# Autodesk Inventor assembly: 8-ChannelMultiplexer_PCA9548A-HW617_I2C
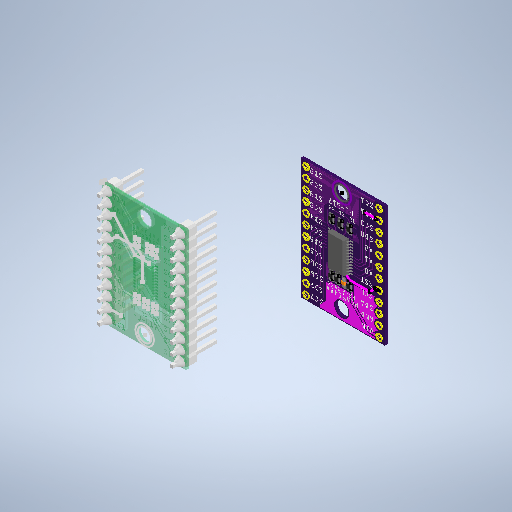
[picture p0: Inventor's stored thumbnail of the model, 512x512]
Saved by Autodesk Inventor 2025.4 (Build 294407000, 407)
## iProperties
Company: unknown
Created: 2023-08
Part Number: 8-ChannelMultiplexer_PCA9548A-HW617_I2C
Document SubType Name: Assembly
Designer: Marcio Valenzuela
Sending System: AutoCAD Architecture 2021 - English
Preprocessor: Autodesk Translation Framework DWG producer (atf_dwg_producer)
Minimum Resolution: 0.01
Sent Units: Millimeter
Translation Standard: IGES 5.3
Model Creation Time: 2023-08-04
Title: 8-ChannelMultiplexer_PCA9548A-HW617_I2C
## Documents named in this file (3)
- C:\Users\Marcio Valenzuela\OneDrive\Documentos\8-ChannelMultiplexer_PCA95.iam
- C:\Users\Marcio Valenzuela\Downloads\8-channelmultiplexer_pca9548a-hw617_i2c-high-detailed-1.snapshot.9\8-ChannelMultiplexer_PCA9548A-HW617_I2C\8-ChannelMultiplexer_PCA9548A-HW617_I2C\8-ChannelMultiplexer_PCA95.iam
- C:\Users\Marcio Valenzuela\Downloads\8-channelmultiplexer_pca9548a-hw617_i2c-high-detailed-1.snapshot.9\8-ChannelMultiplexer_PCA9548A-HW617_I2C\8-ChannelMultiplexer_PCA9548A-HW617_I2C\8-ChannelMultiplexer_PCA95_4.iam
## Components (2 placed, 2 different names)
1. 8D [sub-assembly]
2. 11E [sub-assembly]
